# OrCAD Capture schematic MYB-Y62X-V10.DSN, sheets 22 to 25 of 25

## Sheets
22 PAGE24 - SOM INTERFACE #: size C; note: EXTERNAL INTERFACE
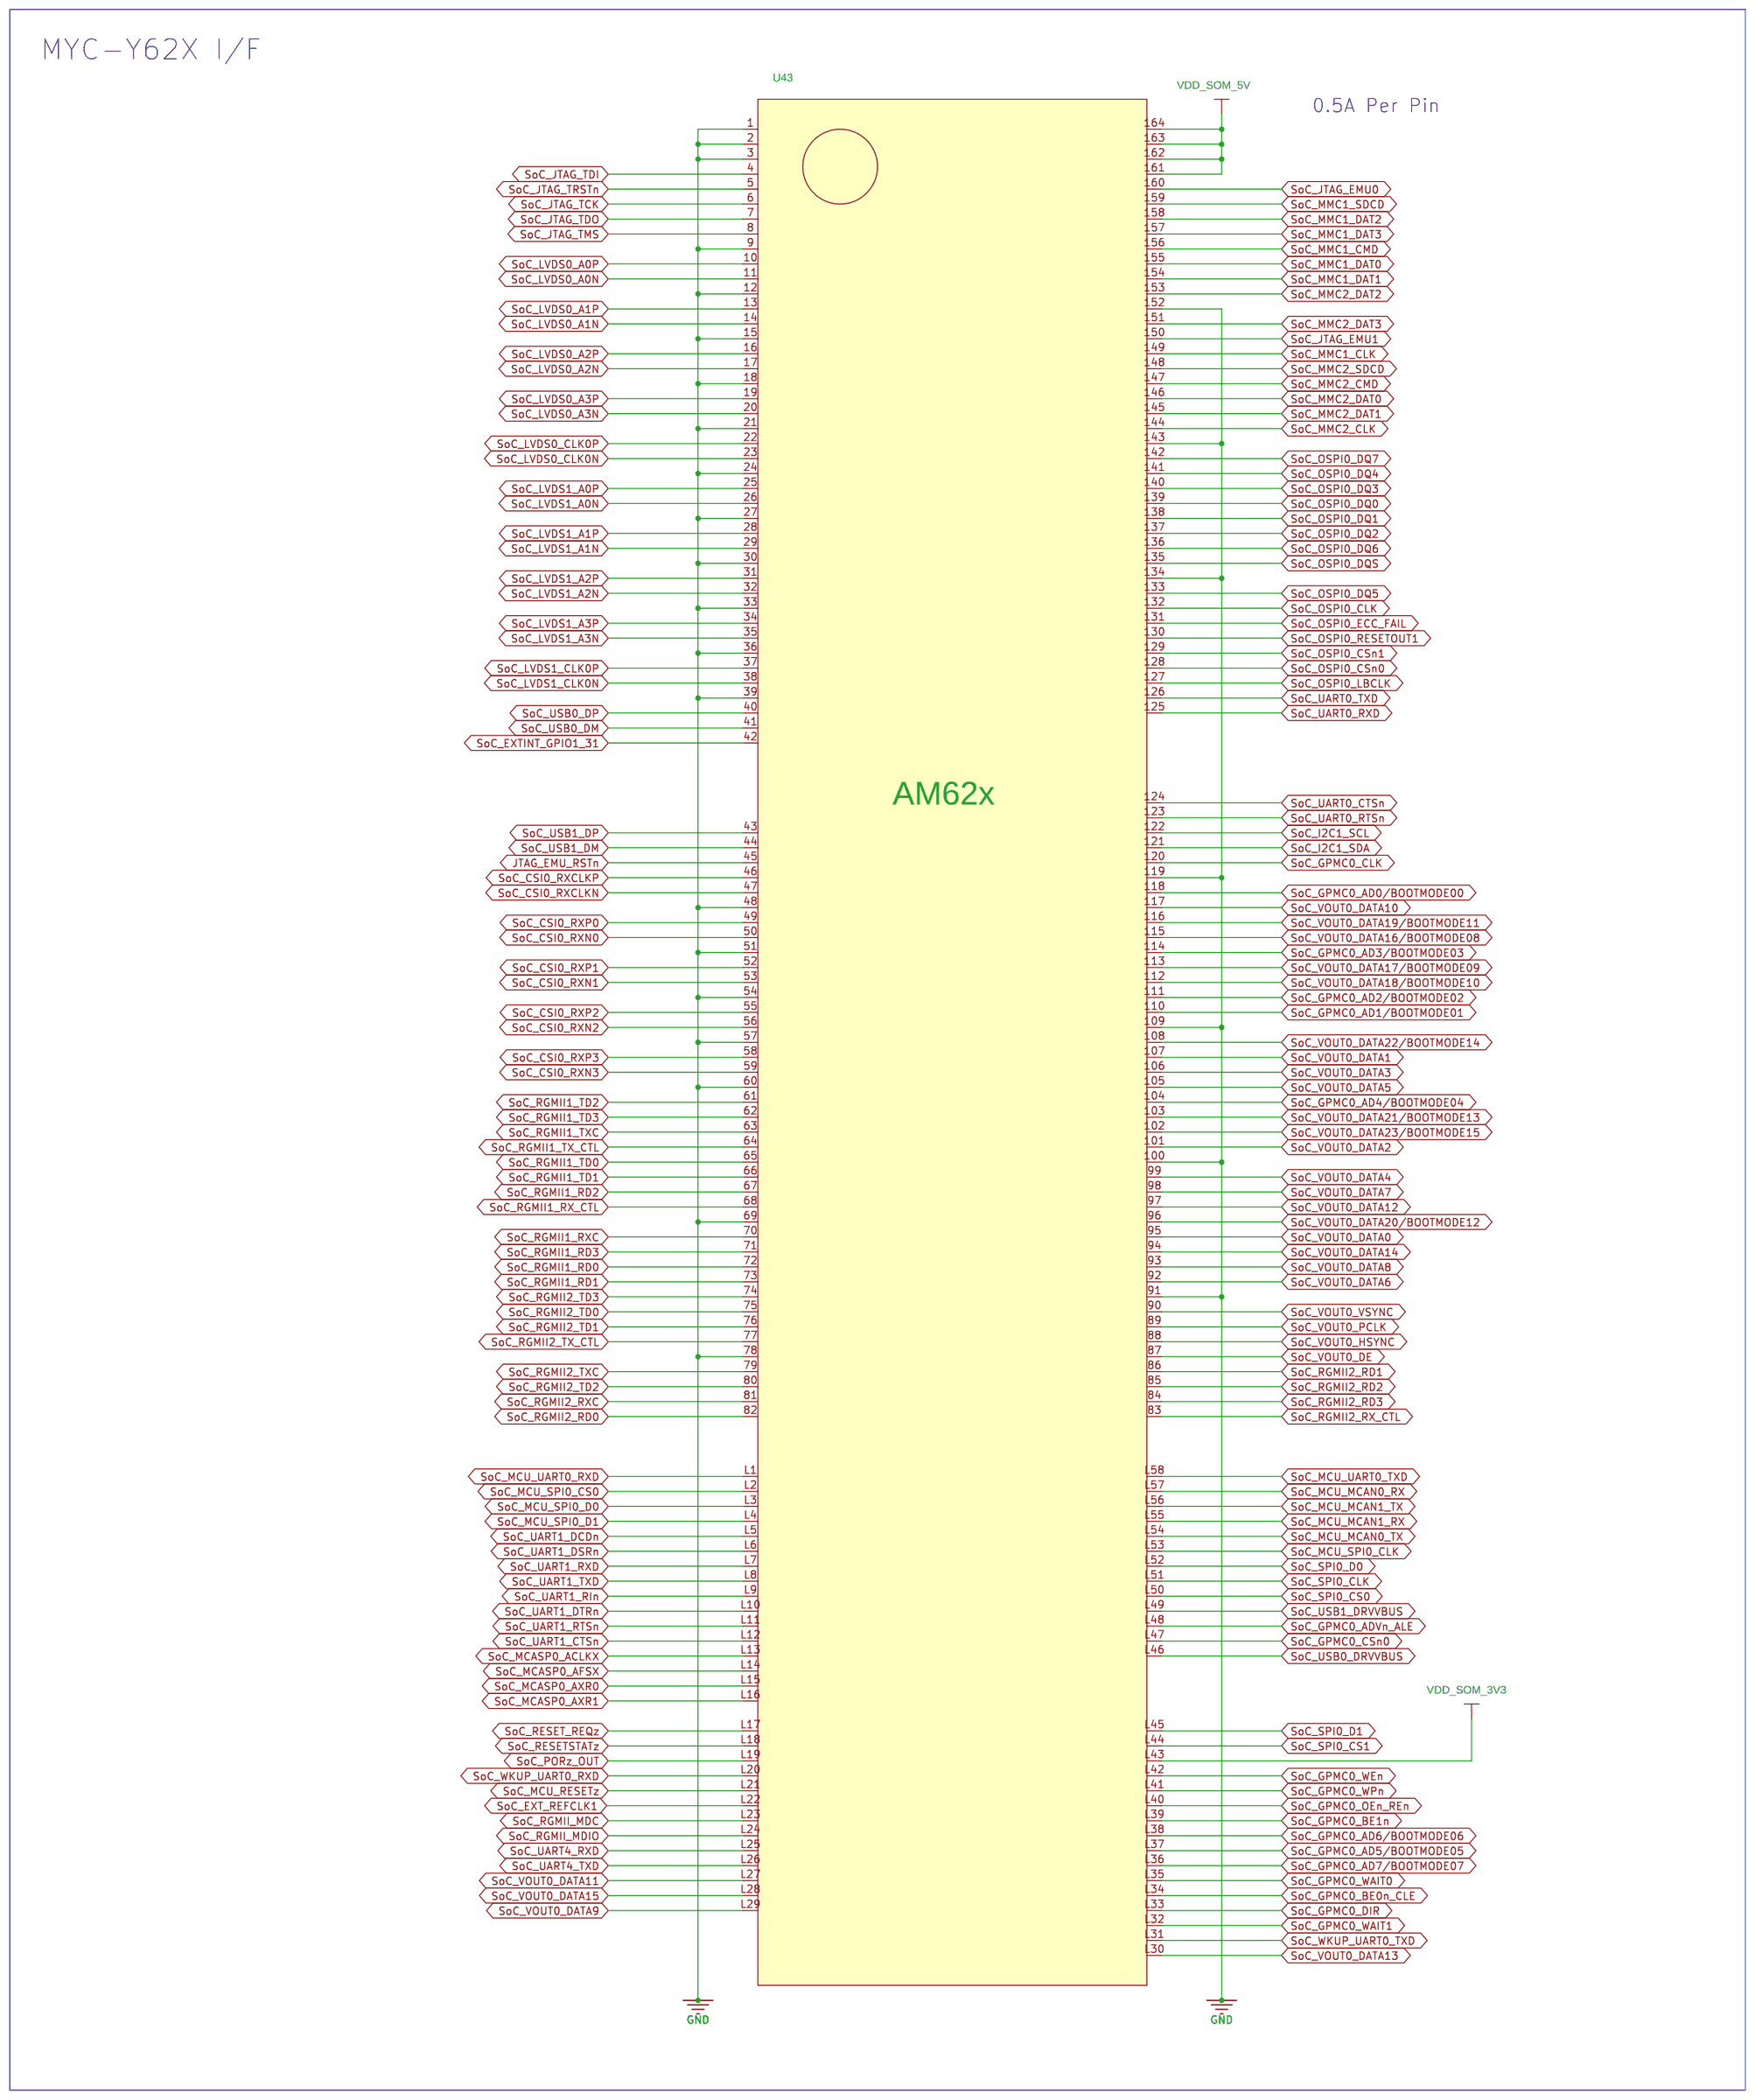
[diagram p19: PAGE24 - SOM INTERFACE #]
23 PAGE25 - ACCESSORIES: size C; note: ACCESSORIES
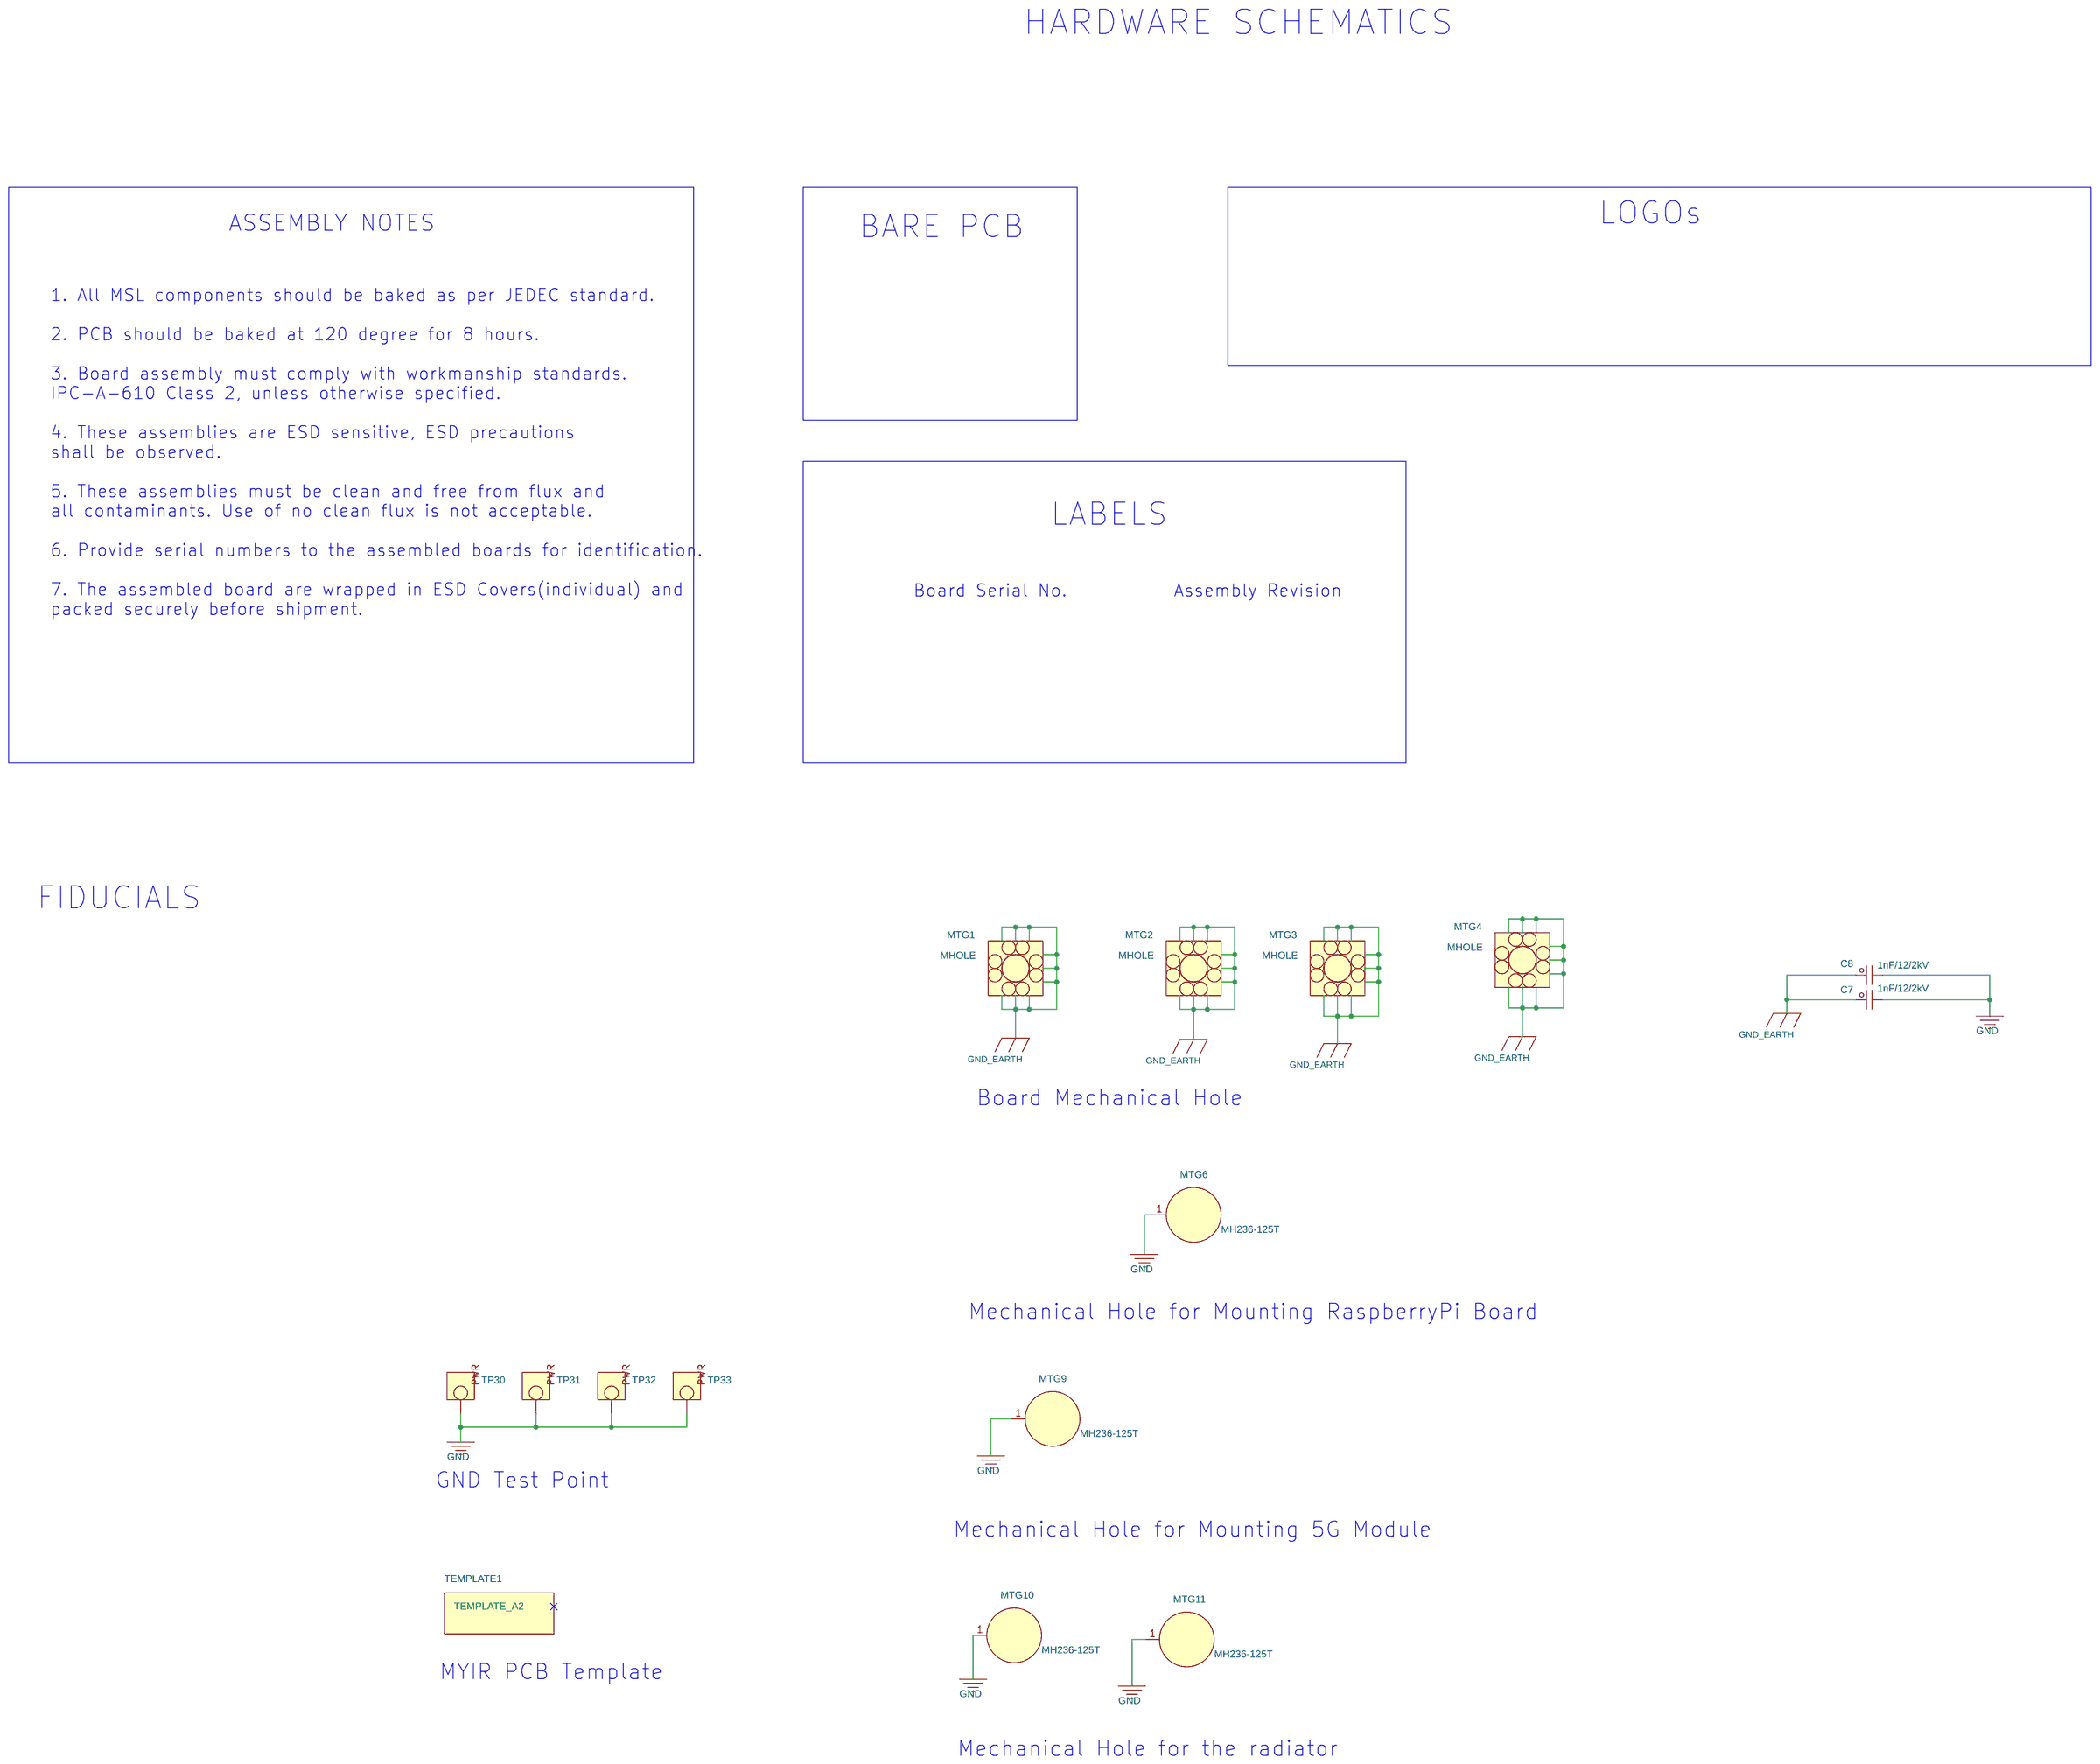
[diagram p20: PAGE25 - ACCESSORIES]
24 PAGE19 - M2 4G/5G MODULE: size A2; note: M2 4G/5G MODULE
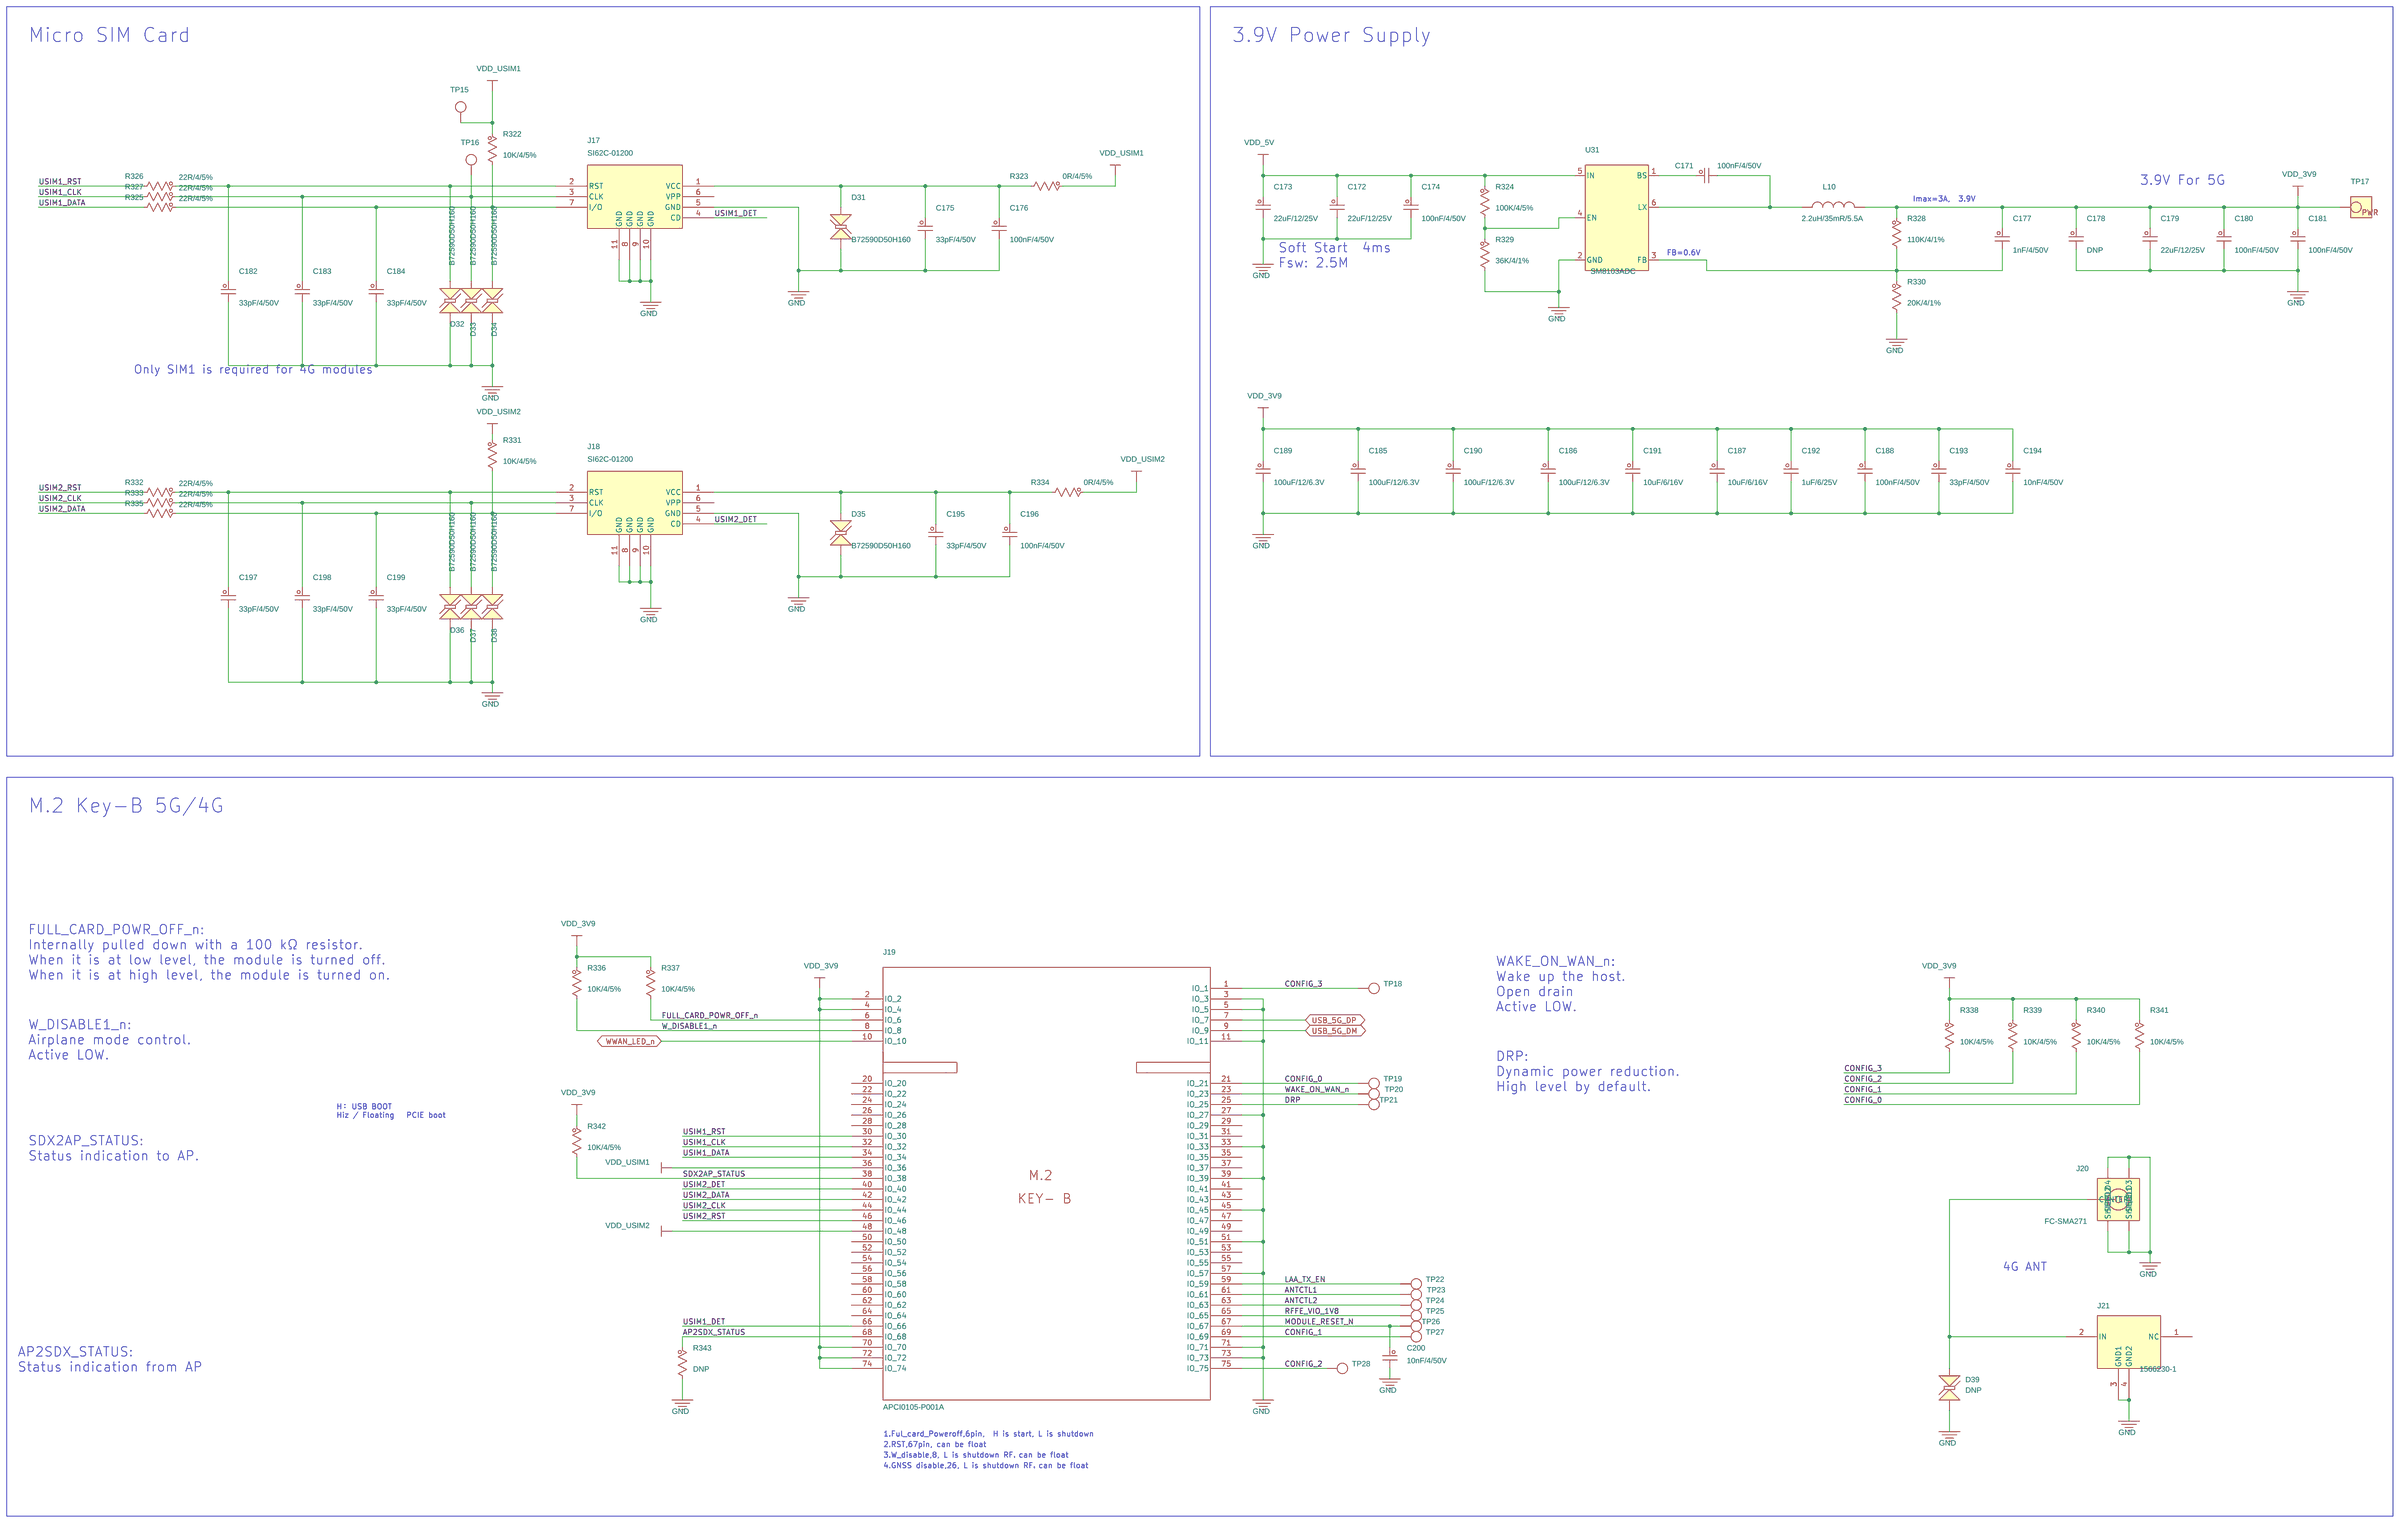
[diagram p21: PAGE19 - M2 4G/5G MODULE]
25 PAGE14 - USB2.0-UART DEBUG I/F#: size B; note: UART2USB DEBUG I/F
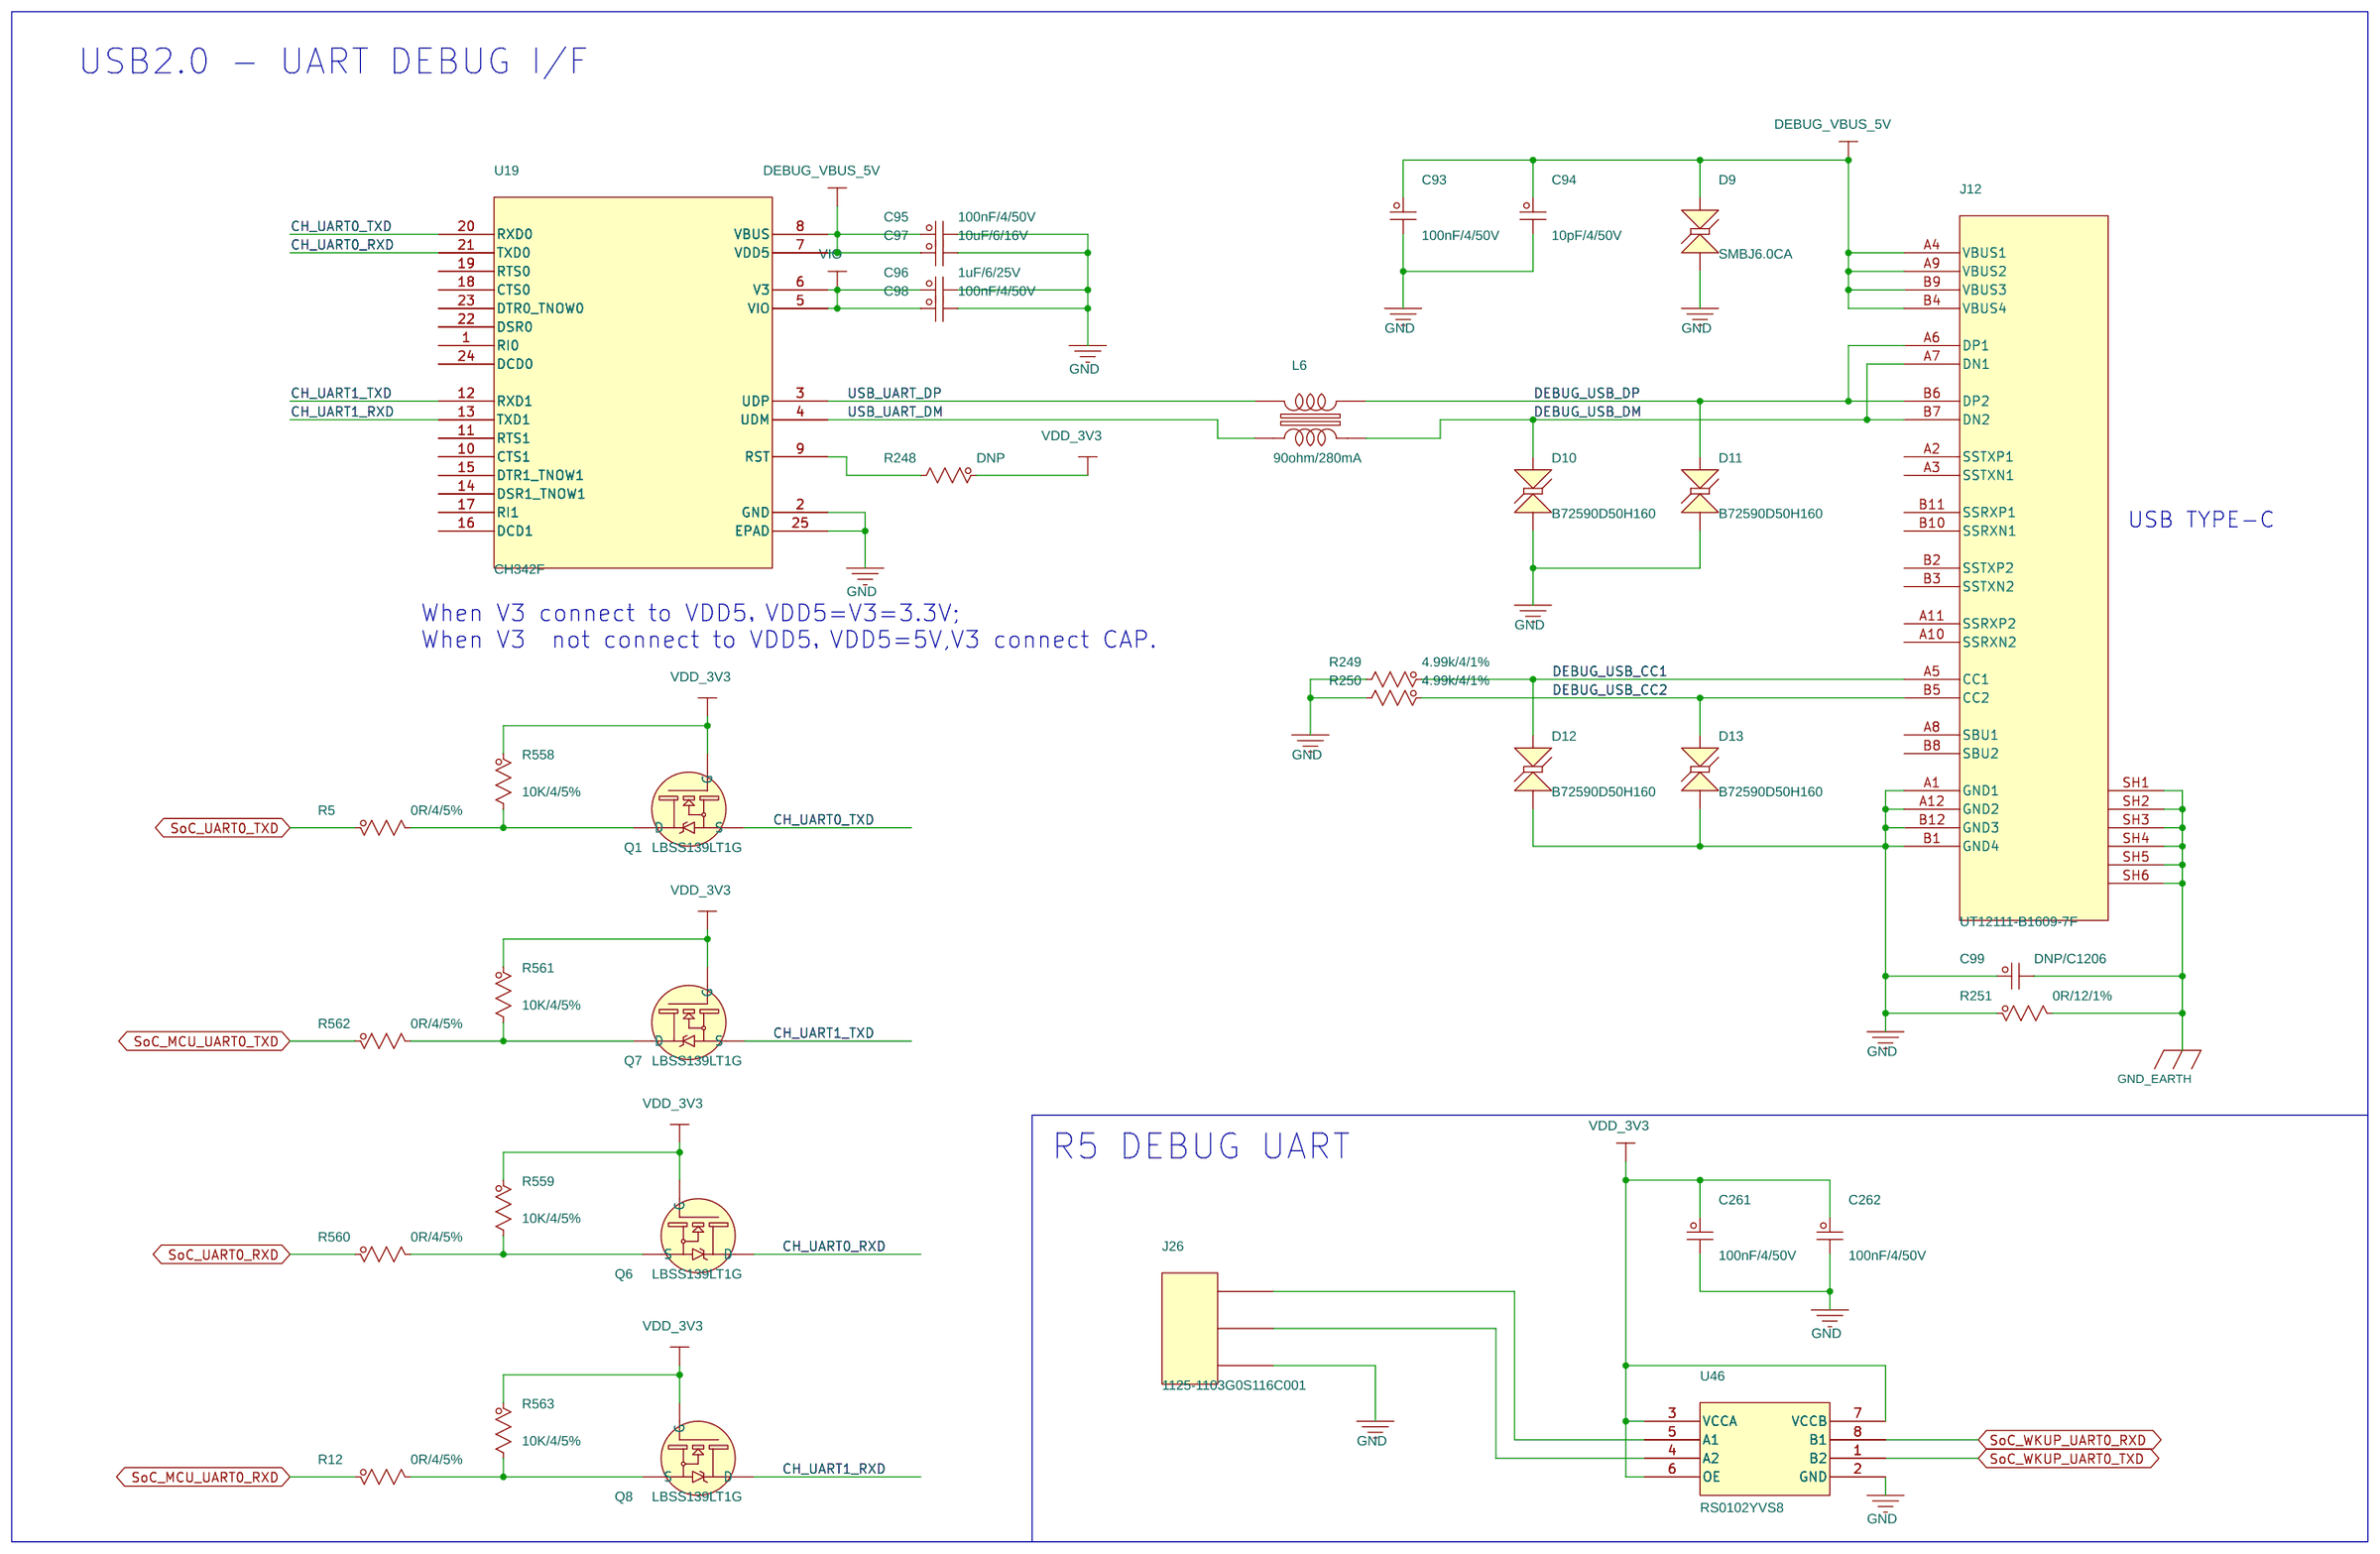
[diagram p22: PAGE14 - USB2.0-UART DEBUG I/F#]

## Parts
sheet PAGE14 - USB2.0-UART DEBUG I/F#
C93  100nF/4/50V  [C0402]
C94  10pF/4/50V  [C0402]
C95  100nF/4/50V  [C0402]
C96  1uF/6/25V  [C0603]
C97  10uF/6/16V  [C0603]
C98  100nF/4/50V  [C0402]
C99  DNP/C1206  [C1206]
C261  100nF/4/50V  [C0402]
C262  100nF/4/50V  [C0402]
D9  SMBJ6.0CA  [DO-214AA]
D10  B72590D50H160  [D0402]
D11  B72590D50H160  [D0402]
D12  B72590D50H160  [D0402]
D13  B72590D50H160  [D0402]
J12  UT12111-B1609-7F  [UT12111-B1609-7F]
J26  1125-1103G0S116C001  [CONN1x3-2_54-DIP]
L6  90ohm/280mA  [indcm-sdcw2012]
Q1  LBSS139LT1G  [SOT-23]
Q6  LBSS139LT1G  [SOT-23]
Q7  LBSS139LT1G  [SOT-23]
Q8  LBSS139LT1G  [SOT-23]
R5  0R/4/5%  [R0402]
R12  0R/4/5%  [R0402]
R248  DNP  [R0402]
R249  4.99k/4/1%  [R0402]
R250  4.99k/4/1%  [R0402]
R251  0R/12/1%  [R1206]
R558  10K/4/5%  [R0402]
R559  10K/4/5%  [R0402]
R560  0R/4/5%  [R0402]
R561  10K/4/5%  [R0402]
R562  0R/4/5%  [R0402]
R563  10K/4/5%  [R0402]
U19  CH342F  [QFN24-0_5]
U46  RS0102YVS8  [VSSOP8]
sheet PAGE19 - M2 4G/5G MODULE
C171  100nF/4/50V  [C0402]
C172  22uF/12/25V  [C1206]
C173  22uF/12/25V  [C1206]
C174  100nF/4/50V  [C0402]
C175  33pF/4/50V  [C0402]
C176  100nF/4/50V  [C0402]
C177  1nF/4/50V  [C0402]
C178  DNP  [C1206]
C179  22uF/12/25V  [C1206]
C180  100nF/4/50V  [C0402]
C181  100nF/4/50V  [C0402]
C182  33pF/4/50V  [C0402]
C183  33pF/4/50V  [C0402]
C184  33pF/4/50V  [C0402]
C185  100uF/12/6.3V  [C1206]
C186  100uF/12/6.3V  [C1206]
C187  10uF/6/16V  [C0603]
C188  100nF/4/50V  [C0402]
C189  100uF/12/6.3V  [C1206]
C190  100uF/12/6.3V  [C1206]
C191  10uF/6/16V  [C0603]
C192  1uF/6/25V  [C0603]
C193  33pF/4/50V  [C0402]
C194  10nF/4/50V  [C0402]
C195  33pF/4/50V  [C0402]
C196  100nF/4/50V  [C0402]
C197  33pF/4/50V  [C0402]
C198  33pF/4/50V  [C0402]
C199  33pF/4/50V  [C0402]
C200  10nF/4/50V  [C0402]
D31  B72590D50H160  [D0402]
D32  B72590D50H160  [D0402]
D33  B72590D50H160  [D0402]
D34  B72590D50H160  [D0402]
D35  B72590D50H160  [D0402]
D36  B72590D50H160  [D0402]
D37  B72590D50H160  [D0402]
D38  B72590D50H160  [D0402]
D39  DNP  [D0402]
J17  SI62C-01200  [SIM-SI62c-01200]
J18  SI62C-01200  [SIM-SI62c-01200]
J19  APCI0105-P001A  [CONN-2199230-3]
J20  FC-SMA271  [ANT-5PINS]
J21  1566230-1  [ANT-1566230-1]
L10  2.2uH/35mR/5.5A  [l5_2x5_5]
R322  10K/4/5%  [R0402]
R323  0R/4/5%  [R0402]
R324  100K/4/5%  [R0402]
R325  22R/4/5%  [R0402]
R326  22R/4/5%  [R0402]
R327  22R/4/5%  [R0402]
R328  110K/4/1%  [R0402]
R329  36K/4/1%  [R0402]
R330  20K/4/1%  [R0402]
R331  10K/4/5%  [R0402]
R332  22R/4/5%  [R0402]
R333  22R/4/5%  [R0402]
R334  0R/4/5%  [R0402]
R335  22R/4/5%  [R0402]
R336  10K/4/5%  [R0402]
R337  10K/4/5%  [R0402]
R338  10K/4/5%  [R0402]
R339  10K/4/5%  [R0402]
R340  10K/4/5%  [R0402]
R341  10K/4/5%  [R0402]
R342  10K/4/5%  [R0402]
R343  DNP  [R0402]
TP15  TPAD_020  [tpad_020]
TP16  TPAD_020  [tpad_020]
TP17  SMD  [HOLE-TP0_9S16]
TP18  TPAD_020  [tpad_020]
TP19  TPAD_020  [tpad_020]
TP20  TPAD_020  [tpad_020]
TP21  TPAD_020  [tpad_020]
TP22  TPAD_020  [tpad_020]
TP23  TPAD_020  [tpad_020]
TP24  TPAD_020  [tpad_020]
TP25  TPAD_020  [tpad_020]
TP26  TPAD_020  [tpad_020]
TP27  TPAD_020  [tpad_020]
TP28  TPAD_020  [tpad_020]
U31  SM8103ADC  [SOT23-6]
sheet PAGE24 - SOM INTERFACE #
U43  AM62x  [myb-youpk43x45_1_00-lga58]
sheet PAGE25 - ACCESSORIES
C7  1nF/12/2kV  [C1206]
C8  1nF/12/2kV  [C1206]
MTG1  MHOLE  [hole3_2p-8]
MTG2  MHOLE  [hole3_2p-8]
MTG3  MHOLE  [hole3_2p-8]
MTG4  MHOLE  [hole3_2p-8]
MTG6  MH236-125T  [MH236-125T]
MTG9  MH236-125T  [MH236-125T]
MTG10  MH236-125T  [GNDPOINT256]
MTG11  MH236-125T  [GNDPOINT256]
TEMPLATE1  TEMPLATE_A2  [TEMPLATE-A2]
TP30  SMD  [HOLE-TP0_9S16]
TP31  SMD  [HOLE-TP0_9S16]
TP32  SMD  [HOLE-TP0_9S16]
TP33  SMD  [HOLE-TP0_9S16]

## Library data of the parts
C93 C95 C98 C171 C174 C176 C180 C181 C188 C196 C261 C262 = Ceramic_Capacitor: Ceramic Capacitor,100nF,50V,+/-10%,X7R,0402,Fenghua; Manufacturer: Fenghua; Manufacturer P/N: 0402B104K500NT; Myir P/N: 20401.80111; Part Type: Ceramic Capacitor; Reserve Value: 100nF; Datasheet: FENGHUA-Capacitor.pdf
C94 = Ceramic_Capacitor: Ceramic Capacitor,10pF,50V,+/-5%,C0G,0402,Fenghua; Manufacturer: Fenghua; Manufacturer P/N: 0402CG100J500NT; Myir P/N: 20401.00076; Part Type: Ceramic Capacitor; Reserve Value: 10pF; Datasheet: FENGHUA-Capacitor.pdf
C96 C192 = Ceramic_Capacitor: Ceramic Capacitor,1uF, 25V,+/-10%,X5R,0603,Samsung; Manufacturer: Samsung; Manufacturer P/N: CL10A105KA8NNNC; Myir P/N: 20401.80063; Part Type: Ceramic Capacitor; Reserve Value: 1uF; Datasheet: Samsung.pdf
C97 C187 C191 = Ceramic_Capacitor: Ceramic Capacitor,10uF,16V,+/-20%,X5R,0603,Samsung; Manufacturer: Samsung; Manufacturer P/N: CL10A106MO8NQNC; Myir P/N: 20401.80062; Part Type: Ceramic Capacitor; Reserve Value: 10uF; Datasheet: Samsung.pdf
C99 = Ceramic_Capacitor: DNP; Manufacturer: DNP; Manufacturer P/N: DNP; Myir P/N: DNP; Part Type: DNP; Reserve Value: DNP; Datasheet: DNP
D9 = TVS_Diode: Diode, TVS Bi-Dir 6V 600W, DO-214AA(SMB); Manufacturer: UN; Myir P/N: 20701.00028; Part Type: Diode; Datasheet: SMBJ6.0C.pdf
D10-D13 D31-D38 = TVS_Diode: Diode,TVS,5.6VDC,SMD,D0402,TDK; Manufacturer: TDK; Myir P/N: 20701.00001; Part Type: Diode; Datasheet: B72590D0050H160.pdf
J12 = UT12111-B1609-7F: Connector,USB C,24Pin,–25℃~＋85℃,SMT,Foxconn; Manufacturer: Foxconn; Myir P/N: 21107.00017; Part Type: USB Connector; Datasheet: USB_C_Foxconn_UT12111-B1609-7F_.pdf
J26 = 1X3PIN: Connector,Pin Header,Straight,Male,1x3Pin,2.54m pitch,11.6,3.0,Gold Flash 1u, black,DIP,Wcon; Manufacturer: Wcon; Myir P/N: 21101.80030; Part Type: Connector; Datasheet: 1125-11XXXXSXXXCXXX.pdf
L6 = Common_Choke: Inductor,Common Choke,90ohm@100MHz,±25%,280mA,0.4ohm,SMD 2*1.2*1.2mm,Sunlord; Manufacturer: Sunlord; Manufacturer P/N: SDCW2012-2-900TF; Myir P/N: 20504.00002; Part Type: Common Inductor; Reserve Value: 90ohm; Datasheet: SDCW2012-2.pdf
Q1 Q6-Q8 = N-MOSFET: Mosfet,N-Channel,50V,0.2A,SMD,SOT-23,LRC; Manufacturer: LRC; Myir P/N: 20703.00012; Part Type: Mosfet; Datasheet: LBSS139LT1G.pdf
R5 R12 R560 R562 = Resister: Thick Film Resistor,0R,+/-5%,1/16W,-55℃~155℃,SMD,0402,Fenghua; Manufacturer: Fenghua; Manufacturer P/N: RC-02000JT; Myir P/N: 20301.00186; Part Type: Thick Film Resistor; Reserve Value: 0R; Datasheet: FHsheet_2018-07-30.PDF
R248 = Resister: Thick Film Resistor,4.7K,+/-5%,1/16W,-55°C ~ 155°C,SMD,0402,Fenghua; Manufacturer: Fenghua; Manufacturer P/N: RC-02W472JT; Myir P/N: 20301.80393; Part Type: Thick Film Resistor; Reserve Value: 4.7K; Datasheet: FHsheet_2018-07-30.PDF
R249 R250 = Resister: Thick Film Resistor,4.99K,+/-1%,,1/16W,-55°C ~ 155°C,,SMD,0402,Fenghua; Manufacturer: Fenghua; Manufacturer P/N: RC-02W4991FT; Myir P/N: 20301.80442; Part Type: Thick Film Resistor; Reserve Value: 4.99K; Datasheet: FHsheet_2018-07-30.PDF
R251 = Resister: Thick Film Resistor,0R,+/-1%,1/4W,-55℃~155℃,SMD,1206,Reel,Fenghua; Manufacturer: Fenghua; Manufacturer P/N: RS-06000FT; Myir P/N: 20301.00312; Part Type: Thick Film Resistor; Reserve Value: 0R; Datasheet: FHsheet-20230524.pdf
R558 R559 R561 R563 = Resister: Thick Film Resistor,10K,+/-5%,1/16W,-55℃~155℃,SMD,0402,Fenghua; Manufacturer: Fenghua; Manufacturer P/N: RC-02W103JT; Myir P/N: 20301.00199; Part Type: Thick Film Resistor; Reserve Value: 10K; Datasheet: FHsheet_2018-07-30.PDF
U19 = CH342F: IC,USB2.0 to Dual UART Ports,-40℃~+85℃,Industrial,SMD,QFN24,CH342F,Qinheng Micro; Manufacturer: Qinheng Micro; Myir P/N: 20107.00089; Part Type: Interface; Datasheet: CH342DS1.pdf
U46 = TXS0102DCT: IC,2-Bit Bidirectional Voltage-Level Translator for Open-Drain and Push-Pull Application,SMD,VSSOP8,Runic; Manufacturer: Runic; Myir P/N: 20105.00030; Part Type: Logic; Datasheet: RS0102.pdf
C172 C173 C179 = Ceramic_Capacitor: Ceramic Capacitor,22uF,25V,+/-10%,X5R,1206,Samsung; Manufacturer: Samsung; Manufacturer P/N: CL31A226KAHNNNE; Myir P/N: 20401.00064; Part Type: Ceramic Capacitor; Reserve Value: 22uF; Datasheet: Samsung.pdf
C175 C182-C184 C193 C195 C197-C199 = Ceramic_Capacitor: Ceramic Capacitor,33pF,50V,+/-5%,C0G,0402,Fenghua; Manufacturer: Fenghua; Manufacturer P/N: 0402CG330J500NT; Myir P/N: 20401.00091; Part Type: Ceramic Capacitor; Reserve Value: 33pF; Datasheet: FENGHUA-Capacitor.pdf
C177 = Ceramic_Capacitor: Ceramic Capacitor,1nF,50V,+/-10%,X7R,0402,Fenghua; Manufacturer: Fenghua; Manufacturer P/N: 0402B102K500NT; Myir P/N: 20401.80096; Part Type: Ceramic Capacitor; Reserve Value: 1nF; Datasheet: FENGHUA-Capacitor.pdf
C178 = Ceramic_Capacitor: Ceramic Capacitor,47uF,10V,+/-20%,X5R,1206,Samsung; Manufacturer: Samsung; Manufacturer P/N: CL31A476MPHNNNE; Myir P/N: 20401.80106; Part Type: Ceramic Capacitor; Reserve Value: 47uF; Datasheet: Samsung.pdf
C185 C186 C189 C190 = Ceramic_Capacitor: Ceramic Capacitor, 100uF,+/-20%,X5R,6.3V,SMD,1206,Samsung; Manufacturer: Samsung; Manufacturer P/N: CL31A107MQHNNNE; Myir P/N: 20401.00095; Part Type: Ceramic Capacitor; Reserve Value: 100uF; Datasheet: Sansung-series.pdf
C194 C200 = Ceramic_Capacitor: Ceramic Capacitor,10nF,50V,+/-10%,X7R,0402,Fenghua; Manufacturer: Fenghua; Manufacturer P/N: 0402B103K500NT; Myir P/N: 20401.80103; Part Type: Ceramic Capacitor; Reserve Value: 10nF; Datasheet: FENGHUA-Capacitor.pdf
D39 = TVS_Diode: Diode,TVS,5.6VDC,SMD,D0402,TDK; Manufacturer: TDK; Manufacturer P/N: B72590D50H160; Myir P/N: 20701.00001; Part Type: Diode; Reserve Value: B72590D50H160; Datasheet: B72590D0050H160.pdf
J17 J18 = SIM-SI62C: Connector,SIM Card,6PIN With  post 1.27mm,H1.35mm,SMD; Manufacturer: Atom; Myir P/N: 21112.80001; Part Type: Card Connector; Datasheet: SI62C-01200.pdf
J19 = PCIEXP_CONN67P_KEY_B: Board Connector,M.2 B-KEY, M.2 Connectors, Connector Height 4.2 mm, Gold, Board-to-Board, 67 Position, 0.5mm,Lotes; Manufacturer: Lotes; Myir P/N: 21110.00027; Part Type: Board Connector; Datasheet: APCI0105-H=4.2(B KEY) .pdf
J20 = SMA-5PIN: Connector,GPS antenna seat  Right Angle GSM 2.4G SMA Gold plated,5Pin  DIP L=1202057mm; Manufacturer: FingXin; Myir P/N: 21114.80007; Part Type: Antenna Connector; Datasheet: FC-SMA271-(1).pdf
J21 = ANT4-0403: Connector,UMCC RCP 0Hz to 6GHz 50Ohm Solder ST SMD Gold Over Nickel,TE; Manufacturer: TE; Myir P/N: 21114.00001; Part Type: Antenna Connector; Datasheet: 1566230-1.pdf
L10 = Inductor: Power Inductor,2.2uH 20%,35mOhm 5.5A ,SMD 5.4*5.2*2.8mm; Manufacturer: Vcoil; Manufacturer P/N: MPH0530-2R2M; Myir P/N: 20501.00020; Part Type: Power Inductor; RP1 Manufacturer P/N: MWSA0503S-2R2MT; RP1 Myir P/N: 20501.00040; Reserve Value: 2.2uH; Datasheet: MPH-Inductor.pdf
R322 R331 R336-R342 = Resister: Thick Film Resistor,10K,+/-5%,1/16W,-55°C ~ 155°C,SMD,0402,Fenghua; Manufacturer: Fenghua; Manufacturer P/N: RC-02W103JT; Myir P/N: 20301.00199; Part Type: Thick Film Resistor; Reserve Value: 10K; Datasheet: FHsheet_2018-07-30.PDF
R323 R334 = Resister: Thick Film Resistor,0R,+/-5%,1/16W,-55°C ~ 155°C,SMD,0402,Fenghua; Manufacturer: Fenghua; Manufacturer P/N: RC-02000JT; Myir P/N: 20301.00186; Part Type: Thick Film Resistor; Reserve Value: 0R; Datasheet: FHsheet_2018-07-30.PDF
R324 R343 = Resister: Thick Film Resistor,100K,+/-5%,,1/16W,-55°C ~ 155°C,SMD,0402,Fenghua; Manufacturer: Fenghua; Manufacturer P/N: RC-02W104JT; Myir P/N: 20301.00210; Part Type: Thick Film Resistor; Reserve Value: 100K; Datasheet: FHsheet_2018-07-30.PDF
R325-R327 R332 R333 R335 = Resister: Thick Film Resistor,22R,+/-5%,1/16W,-55°C ~ 155°C,SMD,0402,Fenghua; Manufacturer: Fenghua; Manufacturer P/N: RC-02W220JT; Myir P/N: 20301.00187; Part Type: Thick Film Resistor; Reserve Value: 22R; Datasheet: FHsheet_2018-07-30.PDF
R328 = Resister: Thick Film Resistor,110K,1%,1/16W ,-55 °C ~155°C ,0402,Fenghua; Manufacturer: Fenghua; Manufacturer P/N: RC-02W1103FT; Myir P/N: 20301.00280; Part Type: Thick Film Resistor; Reserve Value: 110K; Datasheet: FHsheet_2018-07-30.PDF
R329 = Resister: Thick Film Resistor36K,+/-1%,1/16W,-55°C ~ 155°C,SMD,0402,Reel,Fenghua; Manufacturer: Fenghua; Manufacturer P/N: RC-02K3602FT; Myir P/N: 20301.00306; Part Type: Thick Film Resistor; Reserve Value: 36K; Datasheet: FHsheet-20230524.pdf
R330 = Resister: Thick Film Resistor,20K,+/-1%,1/16W,-55°C ~ 155°C,SMD,0402,Fenghua; Manufacturer: Fenghua; Manufacturer P/N: RC-02W2002FT; Myir P/N: 20301.00201; Part Type: Thick Film Resistor; Reserve Value: 20K; Datasheet: FHsheet_2018-07-30.PDF
TP15 TP16 TP18-TP28 = TESTLOOP: TEST POINT PAD 0.5MM DIA SMT, NO PART TO ORDER; AGILE_PN: 211-77484; CAD_APPROVED: Yes; HEIGHT: 0.1MM; ROHS: Yes
TP17 TP30-TP33 = TP_7: DESIG: testing PAD; FAB: NA; REF: NA; VAL: NOT POPULATED
U31 = SM8103ADC: IC,High Efficiency,3.0A,18V Input Synchronous Step Down Regulator,SM8103ADC,SMD,TSOT23-6, Silergy; Manufacturer: Silergy; Myir P/N: 20103.00083; Part Type: Power Management; Datasheet: SM8103ADC.pdf
U43 = MYC-Y15X_0
C7 C8 = Ceramic_Capacitor: Ceramic Capacitor,1nF,+/-10%,2kV,X7R,SMD,1206,Fenghua; Manufacturer: Fenghua; Manufacturer P/N: 1206B102K202NT; Myir P/N: 20401.00078; Part Type: Ceramic Capacitor; Reserve Value: 1nF; Datasheet: FENGHUA-Capacitor.pdf
MTG1-MTG4 = MHOLE_3
MTG6 MTG9-MTG11 = Mounting_Hole_1P: Mounting hole DRILL 125 CIRC PAD 236 PLATED THRU HOLE, NO PART TO ORDER; AGILE_PN: 280-77051; CAD_APPROVED: Yes; HEIGHT: 0.05 MM; MFG_NAME01: none; MFG_PN01: none; ROHS: Yes
TEMPLATE1 = TEMPLATE-A2: Manufacturer: MYIR; Myir P/N: 21122.00032XN; Part Type: Other

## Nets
GND: C7.2 C8.2 C93.2 C94.2 C95.2 C96.2 C97.2 C98.2 C99.1 C172.2 C173.2 C174.2 C175.2 C176.2 C178.2 C179.2 C180.2 C181.2 C182.2 C183.2 C184.2 C185.2 C186.2 C187.2 C188.2 C189.2 C190.2 C191.2 C192.2 C193.2 C194.2 C195.2 C196.2 C197.2 C198.2 C199.2 C200.2 C261.2 C262.2 D9.1 D10.1 D11.1 D12.1 D13.1 D31.1 D32.1 D33.1 D34.1 D35.1 D36.1 D37.1 D38.1 D39.1 J12.A1(GND1) J12.A12(GND2) J12.B1(GND4) J12.B12(GND3) J17.5(GND) J17.8(GND) J17.9(GND) J17.10(GND) J17.11(GND) J18.5(GND) J18.8(GND) J18.9(GND) J18.10(GND) J18.11(GND) J19.3(IO) J19.5(IO) J19.11(IO) J19.27(IO) J19.33(IO) J19.39(IO) J19.45(IO) J19.51(IO) J19.57(IO) J19.71(IO) J19.73(IO) J20.2(SHIELD2) J20.3(SHIELD1) J20.4(SHIELD3) J20.5(SHIELD4) J21.3(GND1) J21.4(GND2) J26.3 MTG6.1 MTG9.1 MTG10.1 MTG11.1 R249.2 R250.2 R251.1 R329.2 R330.2 R343.2 TP30.1(TP) TP31.1(TP) TP32.1(TP) TP33.1(TP) U19.2(GND) U19.25(EPAD) U31.2(GND) U43.1 U43.2 U43.3 U43.9 U43.12 U43.15 U43.18 U43.21 U43.24 U43.27 U43.30 U43.33 U43.36 U43.39 U43.48 U43.51 U43.54 U43.57 U43.60 U43.69 U43.78 U43.91 U43.100 U43.109 U43.119 U43.134 U43.143 U43.152 U46.2(GND) ; also on sheet 1 2 6 7 8 9 10 11 12 13 14 15 16 17 18 19 20 21
GND_EARTH: C7.1 C8.1 C99.2 J12.SH1 J12.SH2 J12.SH3 J12.SH4 J12.SH5 J12.SH6 MTG1.1(GND1) MTG1.2(GND2) MTG1.3(GND3) MTG1.4(GND4) MTG1.5(GND5) MTG1.6(GND6) MTG1.7(GND7) MTG1.8(GND8) MTG1.9(GND9) MTG2.1(GND1) MTG2.2(GND2) MTG2.3(GND3) MTG2.4(GND4) MTG2.5(GND5) MTG2.6(GND6) MTG2.7(GND7) MTG2.8(GND8) MTG2.9(GND9) MTG3.1(GND1) MTG3.2(GND2) MTG3.3(GND3) MTG3.4(GND4) MTG3.5(GND5) MTG3.6(GND6) MTG3.7(GND7) MTG3.8(GND8) MTG3.9(GND9) MTG4.1(GND1) MTG4.2(GND2) MTG4.3(GND3) MTG4.4(GND4) MTG4.5(GND5) MTG4.6(GND6) MTG4.7(GND7) MTG4.8(GND8) MTG4.9(GND9) R251.2 ; also on sheet 6 14 17 18 19
VDD_3V3: C261.1 C262.1 Q1.1(G) Q6.1(G) Q7.1(G) Q8.1(G) R248.1 R558.1 R559.1 R561.1 R563.1 U46.3(VCCA) U46.6(OE) U46.7(VCCB) ; also on sheet 1 2 7 8 10 11 12 13 14 16 17 18 19 20 21
VDD_3V9: C177.1 C178.1 C179.1 C180.1 C181.1 C185.1 C186.1 C187.1 C188.1 C189.1 C190.1 C191.1 C192.1 C193.1 C194.1 J19.2(IO) J19.4(IO) J19.70(IO) J19.72(IO) J19.74(IO) L10.2 R328.1 R336.1 R337.1 R338.1 R339.1 R340.1 R341.1 R342.1 TP17.1(TP)
VDD_5V: C172.1 C173.1 C174.1 R324.1 U31.5(IN) ; also on sheet 1 2 7 12 13 14 17
VDD_SOM_3V3: U43.L43 ; also on sheet 7 15
VDD_SOM_5V: U43.161 U43.162 U43.163 U43.164 ; also on sheet 6
VDD_USIM1: J19.36(IO) R322.1 R323.1 TP15.1(Pin1)
VDD_USIM2: J19.48(IO) R331.1 R334.1
ANTCTL1: J19.61(IO) TP23.1(Pin1)
ANTCTL2: J19.63(IO) TP24.1(Pin1)
AP2SDX_STATUS: J19.68(IO) R343.1
CH_UART0_RXD: Q6.3(D) U19.21(TXD0)
CH_UART0_TXD: Q1.2(S) U19.20(RXD0)
CH_UART1_RXD: Q8.3(D) U19.13(TXD1)
CH_UART1_TXD: Q7.2(S) U19.12(RXD1)
CONFIG_0: J19.21(IO) R341.2 TP19.1(Pin1)
CONFIG_1: J19.69(IO) R340.2 TP27.1(Pin1)
CONFIG_2: J19.75(IO) R339.2 TP28.1(Pin1)
CONFIG_3: J19.1(IO) R338.2 TP18.1(Pin1)
DEBUG_USB_CC1: D12.2 J12.A5(CC1) R249.1
DEBUG_USB_CC2: D13.2 J12.B5(CC2) R250.1
DEBUG_USB_DM: D10.2 J12.A7(DN1) J12.B7(DN2) L6.2
DEBUG_USB_DP: D11.2 J12.A6(DP1) J12.B6(DP2) L6.3
DEBUG_VBUS_5V: C93.1 C94.1 C95.1 C97.1 D9.2 J12.A4(VBUS1) J12.A9(VBUS2) J12.B4(VBUS4) J12.B9(VBUS3) U19.7(VDD5) U19.8(VBUS)
DRP: J19.25(IO) TP21.1(Pin1)
FULL_CARD_POWR_OFF_n: J19.6(IO) R337.2
JTAG_EMU_RSTn: U43.45 ; also on sheet 11
LAA_TX_EN: J19.59(IO) TP22.1(Pin1)
MODULE_RESET_N: C200.1 J19.67(IO) TP26.1(Pin1)
RFFE_VIO_1V8: J19.65(IO) TP25.1(Pin1)
SDX2AP_STATUS: J19.38(IO) R342.2
SoC_CSI0_RXCLKN: U43.47 ; also on sheet 13
SoC_CSI0_RXCLKP: U43.46 ; also on sheet 13
SoC_CSI0_RXN0: U43.50 ; also on sheet 13
SoC_CSI0_RXN1: U43.53 ; also on sheet 13
SoC_CSI0_RXN2: U43.56 ; also on sheet 13
SoC_CSI0_RXN3: U43.59 ; also on sheet 13
SoC_CSI0_RXP0: U43.49 ; also on sheet 13
SoC_CSI0_RXP1: U43.52 ; also on sheet 13
SoC_CSI0_RXP2: U43.55 ; also on sheet 13
SoC_CSI0_RXP3: U43.58 ; also on sheet 13
SoC_EXT_REFCLK1: U43.L22 ; also on sheet 12
SoC_EXTINT_GPIO1_31: U43.42 ; also on sheet 21
SoC_GPMC0_AD0/BOOTMODE00: U43.118 ; also on sheet 14
SoC_GPMC0_AD1/BOOTMODE01: U43.110 ; also on sheet 14
SoC_GPMC0_AD2/BOOTMODE02: U43.111 ; also on sheet 14
SoC_GPMC0_AD3/BOOTMODE03: U43.114 ; also on sheet 14
SoC_GPMC0_AD4/BOOTMODE04: U43.104 ; also on sheet 14
SoC_GPMC0_AD5/BOOTMODE05: U43.L37 ; also on sheet 14
SoC_GPMC0_AD6/BOOTMODE06: U43.L38 ; also on sheet 14
SoC_GPMC0_AD7/BOOTMODE07: U43.L36 ; also on sheet 14
SoC_GPMC0_ADVn_ALE: U43.L48 ; also on sheet 14
SoC_GPMC0_BE0n_CLE: U43.L34 ; also on sheet 14
SoC_GPMC0_BE1n: U43.L39 ; also on sheet 20
SoC_GPMC0_CLK: U43.120 ; also on sheet 14
SoC_GPMC0_CSn0: U43.L47 ; also on sheet 14
SoC_GPMC0_DIR: U43.L33 ; also on sheet 14
SoC_GPMC0_OEn_REn: U43.L40 ; also on sheet 14
SoC_GPMC0_WAIT0: U43.L35 ; also on sheet 14
SoC_GPMC0_WAIT1: U43.L32 ; also on sheet 2
SoC_GPMC0_WEn: U43.L42 ; also on sheet 14
SoC_GPMC0_WPn: U43.L41 ; also on sheet 2
SoC_I2C1_SCL: U43.122 ; also on sheet 21
SoC_I2C1_SDA: U43.121 ; also on sheet 21
SoC_JTAG_EMU0: U43.160 ; also on sheet 11
SoC_JTAG_EMU1: U43.150 ; also on sheet 11
SoC_JTAG_TCK: U43.6 ; also on sheet 11
SoC_JTAG_TDI: U43.4 ; also on sheet 11
SoC_JTAG_TDO: U43.7 ; also on sheet 11
SoC_JTAG_TMS: U43.8 ; also on sheet 11
SoC_JTAG_TRSTn: U43.5 ; also on sheet 11
SoC_LVDS0_A0N: U43.11 ; also on sheet 12
SoC_LVDS0_A0P: U43.10 ; also on sheet 12
SoC_LVDS0_A1N: U43.14 ; also on sheet 12
SoC_LVDS0_A1P: U43.13 ; also on sheet 12
SoC_LVDS0_A2N: U43.17 ; also on sheet 12
SoC_LVDS0_A2P: U43.16 ; also on sheet 12
SoC_LVDS0_A3N: U43.20 ; also on sheet 12
SoC_LVDS0_A3P: U43.19 ; also on sheet 12
SoC_LVDS0_CLK0N: U43.23 ; also on sheet 12
SoC_LVDS0_CLK0P: U43.22 ; also on sheet 12
SoC_LVDS1_A0N: U43.26 ; also on sheet 12
SoC_LVDS1_A0P: U43.25 ; also on sheet 12
SoC_LVDS1_A1N: U43.29 ; also on sheet 12
SoC_LVDS1_A1P: U43.28 ; also on sheet 12
SoC_LVDS1_A2N: U43.32 ; also on sheet 12
SoC_LVDS1_A2P: U43.31 ; also on sheet 12
SoC_LVDS1_A3N: U43.35 ; also on sheet 12
SoC_LVDS1_A3P: U43.34 ; also on sheet 12
SoC_LVDS1_CLK0N: U43.38 ; also on sheet 12
SoC_LVDS1_CLK0P: U43.37 ; also on sheet 12
SoC_MCASP0_ACLKX: U43.L13 ; also on sheet 16
SoC_MCASP0_AFSX: U43.L14 ; also on sheet 16
SoC_MCASP0_AXR0: U43.L15 ; also on sheet 16
SoC_MCASP0_AXR1: U43.L16 ; also on sheet 16
SoC_MCU_MCAN0_RX: U43.L57 ; also on sheet 1
SoC_MCU_MCAN0_TX: U43.L54 ; also on sheet 1
SoC_MCU_MCAN1_RX: U43.L55 ; also on sheet 20
SoC_MCU_MCAN1_TX: U43.L56 ; also on sheet 10
SoC_MCU_RESETz: U43.L21 ; also on sheet 20
SoC_MCU_SPI0_CLK: U43.L53 ; also on sheet 13
SoC_MCU_SPI0_CS0: U43.L2 ; also on sheet 13
SoC_MCU_SPI0_D0: U43.L3 ; also on sheet 13
SoC_MCU_SPI0_D1: U43.L4 ; also on sheet 12
SoC_MCU_UART0_RXD: R12.1 U43.L1
SoC_MCU_UART0_TXD: R562.1 U43.L58
SoC_MMC1_CLK: U43.149 ; also on sheet 8
SoC_MMC1_CMD: U43.156 ; also on sheet 8
SoC_MMC1_DAT0: U43.155 ; also on sheet 8
SoC_MMC1_DAT1: U43.154 ; also on sheet 8
SoC_MMC1_DAT2: U43.158 ; also on sheet 8
SoC_MMC1_DAT3: U43.157 ; also on sheet 8
SoC_MMC1_SDCD: U43.159 ; also on sheet 8
SoC_MMC2_CLK: U43.144 ; also on sheet 10
SoC_MMC2_CMD: U43.147 ; also on sheet 10
SoC_MMC2_DAT0: U43.146 ; also on sheet 10
SoC_MMC2_DAT1: U43.145 ; also on sheet 10
SoC_MMC2_DAT2: U43.153 ; also on sheet 10
SoC_MMC2_DAT3: U43.151 ; also on sheet 10
SoC_MMC2_SDCD: U43.148 ; also on sheet 17
SoC_OSPI0_CLK: U43.132 ; also on sheet 9
SoC_OSPI0_CSn0: U43.128 ; also on sheet 9
SoC_OSPI0_CSn1: U43.129 ; also on sheet 2
SoC_OSPI0_DQ0: U43.139 ; also on sheet 9
SoC_OSPI0_DQ1: U43.138 ; also on sheet 9
SoC_OSPI0_DQ2: U43.137 ; also on sheet 9
SoC_OSPI0_DQ3: U43.140 ; also on sheet 9
SoC_OSPI0_DQ4: U43.141 ; also on sheet 9
SoC_OSPI0_DQ5: U43.133 ; also on sheet 9
SoC_OSPI0_DQ6: U43.136 ; also on sheet 9
SoC_OSPI0_DQ7: U43.142 ; also on sheet 9
SoC_OSPI0_DQS: U43.135 ; also on sheet 9
SoC_OSPI0_ECC_FAIL: U43.131 ; also on sheet 9
SoC_OSPI0_LBCLK: U43.127 ; also on sheet 9
SoC_OSPI0_RESETOUT1: U43.130 ; also on sheet 9
SoC_PORz_OUT: U43.L19 ; also on sheet 18 19
SoC_RESET_REQz: U43.L17 ; also on sheet 20
SoC_RESETSTATz: U43.L18 ; also on sheet 9
SoC_RGMII1_RD0: U43.72 ; also on sheet 18
SoC_RGMII1_RD1: U43.73 ; also on sheet 18
SoC_RGMII1_RD2: U43.67 ; also on sheet 18
SoC_RGMII1_RD3: U43.71 ; also on sheet 18
SoC_RGMII1_RX_CTL: U43.68 ; also on sheet 18
SoC_RGMII1_RXC: U43.70 ; also on sheet 18
SoC_RGMII1_TD0: U43.65 ; also on sheet 18
SoC_RGMII1_TD1: U43.66 ; also on sheet 18
SoC_RGMII1_TD2: U43.61 ; also on sheet 18
SoC_RGMII1_TD3: U43.62 ; also on sheet 18
SoC_RGMII1_TX_CTL: U43.64 ; also on sheet 18
SoC_RGMII1_TXC: U43.63 ; also on sheet 18
SoC_RGMII2_RD0: U43.82 ; also on sheet 19
SoC_RGMII2_RD1: U43.86 ; also on sheet 19
SoC_RGMII2_RD2: U43.85 ; also on sheet 19
SoC_RGMII2_RD3: U43.84 ; also on sheet 19
SoC_RGMII2_RX_CTL: U43.83 ; also on sheet 19
SoC_RGMII2_RXC: U43.81 ; also on sheet 19
SoC_RGMII2_TD0: U43.75 ; also on sheet 19
SoC_RGMII2_TD1: U43.76 ; also on sheet 19
SoC_RGMII2_TD2: U43.80 ; also on sheet 19
SoC_RGMII2_TD3: U43.74 ; also on sheet 19
SoC_RGMII2_TX_CTL: U43.77 ; also on sheet 19
SoC_RGMII2_TXC: U43.79 ; also on sheet 19
SoC_RGMII_MDC: U43.L23 ; also on sheet 18 19
SoC_RGMII_MDIO: U43.L24 ; also on sheet 18 19
SoC_SPI0_CLK: U43.L51 ; also on sheet 12
SoC_SPI0_CS0: U43.L50 ; also on sheet 12
SoC_SPI0_CS1: U43.L44 ; also on sheet 12
SoC_SPI0_D0: U43.L52 ; also on sheet 12
SoC_SPI0_D1: U43.L45 ; also on sheet 12
SoC_UART0_CTSn: U43.124 ; also on sheet 21
SoC_UART0_RTSn: U43.123 ; also on sheet 21
SoC_UART0_RXD: R560.1 U43.125
SoC_UART0_TXD: R5.1 U43.126
SoC_UART1_CTSn: U43.L12 ; also on sheet 10
SoC_UART1_DCDn: U43.L5 ; also on sheet 21
SoC_UART1_DSRn: U43.L6 ; also on sheet 21
SoC_UART1_DTRn: U43.L10 ; also on sheet 1
SoC_UART1_RIn: U43.L9 ; also on sheet 1
SoC_UART1_RTSn: U43.L11 ; also on sheet 10
SoC_UART1_RXD: U43.L7 ; also on sheet 10
SoC_UART1_TXD: U43.L8 ; also on sheet 10
SoC_UART4_RXD: U43.L25 ; also on sheet 2
SoC_UART4_TXD: U43.L26 ; also on sheet 2
SoC_USB0_DM: U43.41 ; also on sheet 17
SoC_USB0_DP: U43.40 ; also on sheet 17
SoC_USB0_DRVVBUS: U43.L46 ; also on sheet 17
SoC_USB1_DM: U43.44 ; also on sheet 17
SoC_USB1_DP: U43.43 ; also on sheet 17
SoC_USB1_DRVVBUS: U43.L49 ; also on sheet 2
SoC_VOUT0_DATA0: U43.95 ; also on sheet 14
SoC_VOUT0_DATA1: U43.107 ; also on sheet 14
SoC_VOUT0_DATA2: U43.101 ; also on sheet 14
SoC_VOUT0_DATA3: U43.106 ; also on sheet 14
SoC_VOUT0_DATA4: U43.99 ; also on sheet 14
SoC_VOUT0_DATA5: U43.105 ; also on sheet 14
SoC_VOUT0_DATA6: U43.92 ; also on sheet 14
SoC_VOUT0_DATA7: U43.98 ; also on sheet 14
SoC_VOUT0_DATA8: U43.93 ; also on sheet 14
SoC_VOUT0_DATA9: U43.L29 ; also on sheet 14
SoC_VOUT0_DATA10: U43.117 ; also on sheet 14
SoC_VOUT0_DATA11: U43.L27 ; also on sheet 14
SoC_VOUT0_DATA12: U43.97 ; also on sheet 14
SoC_VOUT0_DATA13: U43.L30 ; also on sheet 14
SoC_VOUT0_DATA14: U43.94 ; also on sheet 14
SoC_VOUT0_DATA15: U43.L28 ; also on sheet 14
SoC_VOUT0_DATA16/BOOTMODE08: U43.115 ; also on sheet 14
SoC_VOUT0_DATA17/BOOTMODE09: U43.113 ; also on sheet 14
SoC_VOUT0_DATA18/BOOTMODE10: U43.112 ; also on sheet 14
SoC_VOUT0_DATA19/BOOTMODE11: U43.116 ; also on sheet 14
SoC_VOUT0_DATA20/BOOTMODE12: U43.96 ; also on sheet 14
SoC_VOUT0_DATA21/BOOTMODE13: U43.103 ; also on sheet 14
SoC_VOUT0_DATA22/BOOTMODE14: U43.108 ; also on sheet 14
SoC_VOUT0_DATA23/BOOTMODE15: U43.102 ; also on sheet 14
SoC_VOUT0_DE: U43.87 ; also on sheet 14
SoC_VOUT0_HSYNC: U43.88 ; also on sheet 14
SoC_VOUT0_PCLK: U43.89 ; also on sheet 14
SoC_VOUT0_VSYNC: U43.90 ; also on sheet 14
SoC_WKUP_UART0_RXD: U43.L20 U46.8(B1)
SoC_WKUP_UART0_TXD: U43.L31 U46.1(B2)
USB_5G_DM: J19.9(IO) ; also on sheet 17
USB_5G_DP: J19.7(IO) ; also on sheet 17
USB_UART_DM: L6.1 U19.4(UDM)
USB_UART_DP: L6.4 U19.3(UDP)
USIM1_CLK: J19.32(IO) R327.2
USIM1_DATA: J19.34(IO) R325.2
USIM1_DET: J17.4(CD) J19.66(IO)
USIM1_RST: J19.30(IO) R326.2
USIM2_CLK: J19.44(IO) R333.2
USIM2_DATA: J19.42(IO) R335.2
USIM2_DET: J18.4(CD) J19.40(IO)
USIM2_RST: J19.46(IO) R332.2
VIO: C96.1 C98.1 U19.5(VIO) U19.6(V3)
W_DISABLE1_n: J19.8(IO) R336.2
WAKE_ON_WAN_n: J19.23(IO) TP20.1(Pin1)
WWAN_LED_n: J19.10(IO) ; also on sheet 20
N21522281: C182.1 D32.2 J17.2(RST) R326.1
N21522507: C184.1 D34.2 J17.7(I/O) R322.2 R325.1
N21526256: C183.1 D33.2 J17.3(CLK) R327.1 TP16.1(Pin1)
N21526274: C199.1 D38.2 J18.7(I/O) R331.2 R335.1
N21544762: C175.1 C176.1 D31.2 J17.1(VCC) R323.2
N21577420: C171.1 U31.1(BS)
N21577422: C171.2 L10.1 U31.6(LX)
N21577513: R324.2 R329.1 U31.4(EN)
N21577585: C177.2 R328.2 R330.1 U31.3(FB)
N22247036: R248.2 U19.9(RST)
N22404559: C197.1 D36.2 J18.2(RST) R332.1
N22407290: C198.1 D37.2 J18.3(CLK) R333.1
N22680350: J26.1 U46.5(A1)
N22680357: J26.2 U46.4(A2)
N22941387: Q1.3(D) R5.2 R558.2
N22941439: Q6.2(S) R559.2 R560.2
N22941491: Q7.3(D) R561.2 R562.2
N22941543: Q8.2(S) R12.2 R563.2
N24926165: C195.1 C196.1 D35.2 J18.1(VCC) R334.2
N25388780: D39.2 J20.1(CENTER1) J21.2(IN)

Not connected (* = marked no-connect by the designer): J12 A2(SSTXP1) A3(SSTXN1) A8(SBU1) A10(SSRXN2) A11(SSRXP2) B2(SSTXP2) B3(SSTXN2) B8(SBU2) B10(SSRXN1) B11(SSRXP1); J17 6(VPP); J18 6(VPP); J19 20(IO) 22(IO) 24(IO) 26(IO) 28(IO) 29(IO) 31(IO) 35(IO) 37(IO) 41(IO) 43(IO) 47(IO) 49(IO) 50(IO) 52(IO) 53(IO) 54(IO) 55(IO) 56(IO) 58(IO) 60(IO) 62(IO) 64(IO); J21 1(NC); TEMPLATE1 1*; U19 1(RI0) 10(CTS1) 11(RTS1) 14(DSR1_TNOW1) 15(DTR1_TNOW1) 16(DCD1) 17(RI1) 18(CTS0) 19(RTS0) 22(DSR0) 23(DTR0_TNOW0) 24(DCD0)

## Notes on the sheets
sheet 22
- MYC-Y62X I/F
- 0.5A Per Pin
sheet 23
- HARDWARE SCHEMATICS
- LOGOs
- ASSEMBLY NOTES
- BARE PCB
- 1. All MSL components should be baked as per JEDEC standard.
  2. PCB should be baked at 120 degree for 8 hours.
  3. Board assembly must comply with workmanship standards.
  IPC-A-610 Class 2, unless otherwise specified.
  4. These assemblies are ESD sensitive, ESD precautions
  shall be observed.
  5. These assemblies must be clean and free from flux and
  all contaminants. Use of no clean flux is not acceptable.
  6. Provide serial numbers to the assembled boards for identification.
  7. The assembled board are wrapped in ESD Covers(individual) and
  packed securely before shipment.
- LABELS
- Board Serial No.
- Assembly Revision
- FIDUCIALS
- Board Mechanical Hole
- Mechanical Hole for Mounting RaspberryPi Board
- GND Test Point
- Mechanical Hole for Mounting 5G Module
- MYIR PCB Template
- Mechanical Hole for the radiator
sheet 24
- Micro SIM Card
- 3.9V Power Supply
- 3.9V For 5G
- Imax=3A,
- 3.9V
- Soft Start  4ms
  Fsw: 2.5M
- FB=0.6V
- Only SIM1 is required for 4G modules
- M.2 Key-B 5G/4G
- FULL_CARD_POWR_OFF_n:
  Internally pulled down with a 100 kΩ resistor.
  When it is at low level, the module is turned off.
  When it is at high level, the module is turned on.
- WAKE_ON_WAN_n:
  Wake up the host.
  Open drain
  Active LOW.
- W_DISABLE1_n:
  Airplane mode control.
  Active LOW.
- DRP:
  Dynamic power reduction.
  High level by default.
- H： USB BOOT
  Hiz / Floating   PCIE boot
- SDX2AP_STATUS:
  Status indication to AP.
- 4G ANT
- AP2SDX_STATUS:
  Status indication from AP
- 1.Ful_card_Poweroff,6pin,  H is start, L is shutdown
- 2.RST,67pin, can be float
- 3.W_disable,8, L is shutdown RF，can be float
- 4.GNSS disable,26, L is shutdown RF，can be float
sheet 25
- USB2.0 - UART DEBUG I/F
- USB TYPE-C
- When V3 connect to VDD5，VDD5=V3=3.3V;
  When V3  not connect to VDD5，VDD5=5V,V3 connect CAP.
- R5 DEBUG UART
